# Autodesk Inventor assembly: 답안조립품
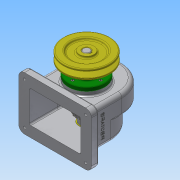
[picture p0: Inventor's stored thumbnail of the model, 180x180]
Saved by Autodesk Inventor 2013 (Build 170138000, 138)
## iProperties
Created: 2017-11
Part Number: 답안조립품
Document SubType Name: Assembly
Designer: Administrator
Author: Administrator
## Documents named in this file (14)
- C:\Users\Administrator\Desktop\471108V1031\답안조립품.iam
- C:\Users\Administrator\Desktop\471108V1031\V-벨트풀리.ipt
- C:\Users\Administrator\Desktop\471108V1031\뒤커버.ipt
- C:\Users\Administrator\Desktop\471108V1031\멈춤나사 - M4 x 10.ipt
- 멈춤나사 - M4 x 10.ipt
- C:\Users\Administrator\Desktop\471108V1031\베어링 6002.ipt
- C:\Users\Administrator\Desktop\471108V1031\본체.ipt
- C:\Users\Administrator\Desktop\471108V1031\볼트 M3 x 8.ipt
- C:\Users\Administrator\Desktop\471108V1031\스퍼기어.ipt
- C:\Users\Administrator\Desktop\471108V1031\앞커버.ipt
- C:\Users\Administrator\Desktop\471108V1031\오일 실 15 30 7.ipt
- C:\Users\Administrator\Desktop\471108V1031\축.ipt
- C:\Users\Administrator\Desktop\471108V1031\키 - 5 x 5 x 18.ipt
- C:\Users\Administrator\Desktop\471108V1031\키 - 6 x 6 x 22.ipt
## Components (1 placed, 1 different names)
1. V-벨트풀리:1
